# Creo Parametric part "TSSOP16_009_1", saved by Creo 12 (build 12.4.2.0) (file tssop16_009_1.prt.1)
Units: Custom; MM, KILOGRAM, SECS

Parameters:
  PTC_WM_ITERATION = "0"
  PTC_WM_VERSION = "-.0"
  PTC_WM_LIFECYCLE_STATE = "In Work"
  PTC_WM_LIFECYCLE = "MO_CADDocument"
  PTC_WM_CREATED_BY = "Maximilian Roepper (Z0017RMS: MO)"
  PTC_WM_CREATED_ON = "18-Sep-26 11:36:42 AM"
  PTC_WM_MODIFIED_BY = "Maximilian Roepper (Z0017RMS: MO)"
  PTC_WM_MODIFIED_ON = "18-Sep-26 11:36:46 AM"
  PDMLINKNUMBER = "PDM000071455315"
  PTC_WM_NAME = "tssop16_009_1.prt"
  PTC_WM_NUMBER = "PDM000071455315"

Other parameters: WEIGHT, WEIGHT_FACTOR, WEIGHT_ADD, _MASS_TEMP, _DIFF_TEMP, MC_ERRORS, SUPPLIER

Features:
  1. coordinate system
  2. datum plane "PRT_YZ"
  3. datum plane "PRT_XY"
  4. datum plane "PRT_XZ"
  5. coordinate system
  6. datum axis
  7. datum axis
  8. datum axis
  9. coordinate system
  10. imported feature

Other named items: PRT, SIEMENS_MO, DRW_VIEW_ORG, PRT_X, PRT_Y, PRT_Z, CS0, ROUGH_GROB

Layers: 00_STD_CSYS-KSYS, 01_STD_PLANES-EBENEN, 02_STD_AXES-ACHSEN, 03_STD_CSYS-KSYS, 24_IMPORT_FEAT-IMPORT_KE

Surfaces: 14 plane, 8 cylinder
